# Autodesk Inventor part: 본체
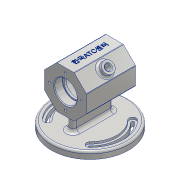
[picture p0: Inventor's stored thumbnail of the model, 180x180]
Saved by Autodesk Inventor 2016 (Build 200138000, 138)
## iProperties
Created: 2017-06
Part Number: 본체
Material: 알루미늄 6061
Document SubType Name: Modeling
Designer: KSEW
Density: 2.7 g/cm^3
Appearance: 알루미늄 - 평지
Mass: 560.19 g
Surface Area: 566.116 cm^2
Volume: 207.478 cm^3
Author: KSEW
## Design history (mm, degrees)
sketch "스케치1"
  geometry: L1 (30, -12.426)-(12.426, -30); L2 (12.426, -30)-(-12.426, -30); L3 (-12.426, -30)-(-30, -12.426); L4 (-30, -12.426)-(-30, 12.426); L5 (-30, 12.426)-(-12.426, 30); L6 (-12.426, 30)-(12.426, 30); L7 (12.426, 30)-(30, 12.426); L8 (30, 12.426)-(30, -12.426); C1 r 30 at (0, 0); 3 further points
  constraints: 16 end point, 2 coincident, 1 centre point, 1 midpoint, 1 vertical alignment, 17 other
  dimensions: "d0" = 60 diameter of C1; "d1" = 30 distance from line of point (0, 0) L4
extrude "돌출1" new body sketch "스케치1" stored distance "d2" = 70; taper "d3" = 0 deg
sketch "스케치2"
  geometry: 2 further points
  constraints: 1 vertical alignment
  dimensions: "d4" = 23 distance of point (0, 0) point (0, 23)
hole "구멍1" sketch "스케치2" at (0, 23) diameter "d5" = 3.459; stored, may be unused: countersink angle "d9" = 90 deg, drill point angle "d11" = 118 deg; dims "d6" = 8, "d7" = 4, "d8" = 2, "d10" = 10
sketch "스케치3"
  geometry: L1 (0, 0)-(0, 30); L2 (-26.163, 26.163)-(0, 0); L3 (-26.163, 26.163)-(-20.506, 31.82); L4 (-12.426, 30)-(-30, 12.426) reference; L5 (-26.163, 26.163)-(-20.506, 31.82); L6 (-20.506, 31.82)-(-15.556, 26.87); L7 (-15.556, 26.87)-(-21.213, 21.213); L8 (-21.213, 21.213)-(-26.163, 26.163)
  constraints: 14 end point, 3 parallel, 1 collinear, 1 perpendicular, 1 vertical
  dimensions: "d12" = 45 deg angle of L1 L2; "d13" = 8 distance of L2.start L3.end; "d14" = 7 distance from line of L2.start L4; "d15" = 30 distance of L1.start L1.end; "d16" = 7 distance of L3.end L6.end (= d14)
revolve "회전1" sketch "스케치3" stored, may be unused: angle "d17" = 90 deg
node "작업 평면1"
sketch "스케치4"
  geometry: C1 r 55 at (0, 0); 1 further point
  constraints: 1 centre point, 1 coincident
  dimensions: "d19" = 110 diameter of C1
extrude "돌출2" join sketch "스케치4" distance "d20" = 10; taper "d21" = 0 deg
sketch "스케치5"
  geometry: L1 (0, -24)-(0, 24); L2 (5, -24)-(5, 24); L3 (-5, 24)-(-5, -24); C1 r 55 at (0, 0) reference; A1 r 5 centre (0, -24) between (-5, -24) and (5, -24); A2 r 5 centre (0, 24) between (5, 24) and (-5, 24); 1 further point
  constraints: 8 end point, 4 point on circle, 4 tangent, 2 centre point, 1 coincident, 1 midpoint, 1 parallel, 1 vertical
  dimensions: "d22" = 5 radius of A1; "d23" = 48 distance of L1.end L1.start
extrude "돌출3" join sketch "스케치5" stored distance "d24" = 10; taper "d25" = 0 deg
sketch "스케치6"
  geometry: L1 (-30.406, 30.406)-(0, 0); L2 (-30.406, -30.406)-(0, 0); L3 (-43, 0)-(0, 0); C1 r 55 at (0, 0) reference; A1 r 43 centre (0, 0) between (-30.406, 30.406) and (-30.406, -30.406); A2 r 43 centre (0, 0) between (-30.406, 30.406) and (-30.406, -30.406); A3 r 48 centre (0, 0) between (-33.941, 33.941) and (-33.941, -33.941); A4 r 38 centre (0, 0) between (-26.87, 26.87) and (-26.87, -26.87); A5 r 5 centre (-30.406, 30.406) between (-26.87, 26.87) and (-33.941, 33.941); A6 r 5 centre (-30.406, -30.406) between (-33.941, -33.941) and (-26.87, -26.87)
  constraints: 14 point on circle, 6 centre point, 6 end point, 4 tangent, 2 coincident, 1 horizontal
  dimensions: "d28" = 86 diameter of A1; "d31" = 45 deg angle of L3 L2; "d32" = 90 deg angle of L1 L2; "d33" = 48 radius of A3
extrude "돌출4" cut sketch "스케치6" distance "d34" = 3; taper "d35" = 0 deg
sketch "스케치7"
  geometry: A1 r 48 centre (0, 0) between (-33.941, 33.941) and (-33.941, -33.941) reference; A2 r 5 centre (-30.406, -30.406) between (-33.941, -33.941) and (-26.87, -26.87) reference; A3 r 38 centre (0, 0) between (-26.87, 26.87) and (-26.87, -26.87) reference; A4 r 5 centre (-30.406, 30.406) between (-26.87, 26.87) and (-33.941, 33.941) reference; A5 r 45 centre (0, 0) between (-31.82, 31.82) and (-31.82, -31.82); A6 r 2 centre (-30.406, 30.406) between (-28.991, 28.991) and (-31.82, 31.82); A7 r 41 centre (0, 0) between (-28.991, 28.991) and (-28.991, -28.991); A8 r 2 centre (-30.406, -30.406) between (-31.82, -31.82) and (-28.991, -28.991)
  constraints: 8 point on circle, 4 centre point, 3 other
  dimensions: "d36" = 2 radius of A6
extrude "돌출5" cut sketch "스케치7" stored distance "d37" = 3; taper "d38" = 0 deg
sketch "스케치8"
  geometry: L1 (-35, 16)-(-23, 16); L2 (-23, 16)-(-23, 0); L3 (-23, 0)-(-35, 0); L4 (-35, 0)-(-35, 16); L5 (23, 16)-(35, 16); L6 (35, 16)-(35, 0); L7 (35, 0)-(23, 0); L8 (23, 0)-(23, 16); L9 (-17, 25)-(17, 25); L10 (20, 22)-(20, 0); L11 (20, 0)-(-20, 0); L12 (-20, 0)-(-20, 22); L13 (-35, -12.426)-(-35, 12.426) reference; L14 (35, 12.426)-(35, -12.426) reference; A1 r 3 centre (-17, 22) between (-17, 25) and (-20, 22); A2 r 3 centre (17, 22) between (20, 22) and (17, 25); 4 further points
  constraints: 24 end point, 6 parallel, 5 point on line, 4 point on circle, 4 tangent, 3 horizontal, 3 perpendicular, 2 centre point, 2 horizontal alignment, 1 coincident, 1 equal radius, 1 midpoint
  dimensions: "d39" = 12 distance of L1.start L1.end; "d40" = 12 distance of L5.start L5.end; "d41" = 40 distance of point (-20, 25) point (20, 25); "d42" = 16 distance of L3.end L1.start; "d43" = 16 distance of L5.end L6.end; "d44" = 25 distance of point (20, 25) L10.end; "d45" = 0 distance between parallel lines of L4 L13; "d46" = 0 distance between parallel lines of L14 L6; "d47" = 3 radius of A1
revolve "회전2" sketch "스케치8" stored, may be unused: angle "d48" = 90 deg
sketch "스케치9"
  geometry: C1 r 14 at (0, 0); 1 further point
  constraints: 1 centre point, 1 coincident
  dimensions: "d49" = 28 diameter of C1
extrude "돌출6" cut sketch "스케치9" stored distance "d50" = 70; taper "d51" = 0 deg
fillet "모깎기1" dims "d52" = 0.3
chamfer "모따기1" distance "d53" = 1; stored, may be unused: second distance "d54" = 2, angle "d55" = 45 deg
chamfer "모따기2" distance "d56" = 1; stored, may be unused: second distance "d57" = 2, angle "d58" = 45 deg
sketch "스케치10"
  geometry: C1 r 8 at (0, 0) reference; 1 further point
  constraints: 1 coincident
hole "구멍2" sketch "스케치10" at (0, 0) diameter "d62" = 8; stored, may be unused: countersink angle "d66" = 90 deg, drill point angle "d68" = 118 deg; dims "d63" = 8, "d64" = 4, "d65" = 2, "d67" = 30
chamfer "모따기3" distance "d69" = 1; stored, may be unused: second distance "d70" = 2, angle "d71" = 45 deg
sketch "스케치11"
  geometry: L1 (24.853, -70)-(0, -70) reference; L2 (-17.574, 0)-(-17.574, -70) reference; 2 further points
  constraints: 1 other
  dimensions: "d72" = 35 distance from line of point (12.426, -35) L1; "d73" = 30 distance from line of point (12.426, -35) L2
feature "엠보싱1" sketch "스케치11" dims "d74" = 0.5, "d75" = 0
fillet "모깎기2" dims "d76" = 3
fillet "모깎기3" dims "d77" = 5
fillet "모깎기4" dims "d78" = 3
fillet "모깎기5" dims "d79" = 1
node "솔리드1"
mirror "대칭1"
pattern_circular "원형 패턴1" dims angle "d60" = 360 deg
mirror "대칭2"
other parameters: "d18" = -62, "d29" = 45 deg, "d30" = 45 deg
